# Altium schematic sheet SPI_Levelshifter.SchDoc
size A4
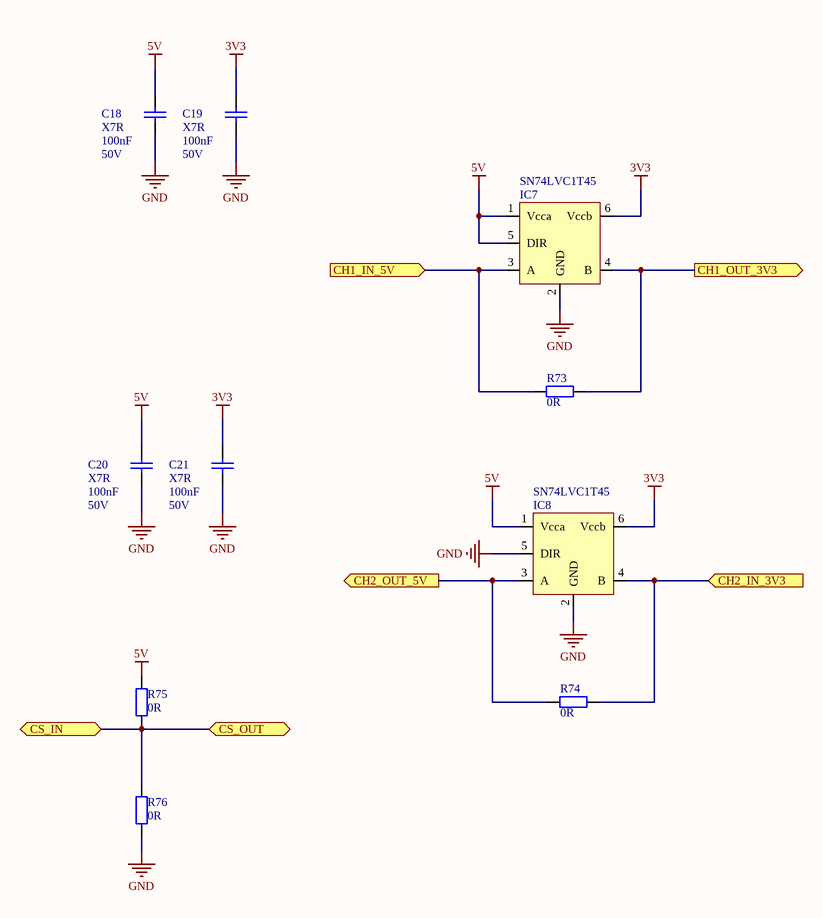
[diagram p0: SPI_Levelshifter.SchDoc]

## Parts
C18  A_Charakteristik: X7R  L_Spannung: 50V  [RLCDT_0805]  (hidden comment: 100nF)
C19  A_Charakteristik: X7R  L_Spannung: 50V  [RLCDT_0805]  (hidden comment: 100nF)
C20  A_Charakteristik: X7R  L_Spannung: 50V  [RLCDT_0805]  (hidden comment: 100nF)
C21  A_Charakteristik: X7R  L_Spannung: 50V  [RLCDT_0805]  (hidden comment: 100nF)
IC7  SN74LVC1T45  [IC_SOT23-6]
IC8  SN74LVC1T45  [IC_SOT23-6]
R73  0R  [RLCDT_0805]
R74  0R  [RLCDT_0805]
R75  0R  [RLCDT_0805]
R76  0R  [RLCDT_0805]

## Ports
CH1_IN_5V (in), CH1_OUT_3V3 (out), CH2_IN_3V3 (in), CH2_OUT_5V (out), CS_IN, CS_OUT

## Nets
3V3: C19.1 C21.1 IC7.6(Vccb) IC8.6(Vccb)
5V: C18.1 C20.1 IC7.1(Vcca) IC7.5(DIR) IC8.1(Vcca) R75.2
GND: C18.2 C19.2 C20.2 C21.2 IC7.2(GND) IC8.2(GND) IC8.5(DIR) R76.1
CH1_IN_5V: IC7.3(A) R73.2 ; port CH1_IN_5V
CH1_OUT_3V3: IC7.4(B) R73.1 ; port CH1_OUT_3V3
CH2_IN_3V3: IC8.4(B) R74.1 ; port CH2_IN_3V3
CH2_OUT_5V: IC8.3(A) R74.2 ; port CH2_OUT_5V
CS_IN: R75.1 R76.2 ; port CS_IN, port CS_OUT

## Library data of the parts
C18-C21 = C_KERAMIK: Kondensator, Keramik; W_Erstellt: MRipel; A_Wichtiger_Hinweis: optional; H_Temp_min: ?°C; J_Richtpreis_10: 0,00; G_Wird_beigestellt: Nein; A_Update_From_DB: Ja; A_Database_ID: not updated
R73-R76 = R: Widerstand; W_Erstellt: MRipel; A_Wichtiger_Hinweis: optional; L_Spannung: 50V; H_Temp_min: ?°C; J_Richtpreis_10: 0,00; G_Wird_beigestellt: Nein; A_Update_From_DB: Ja; A_Database_ID: not updated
